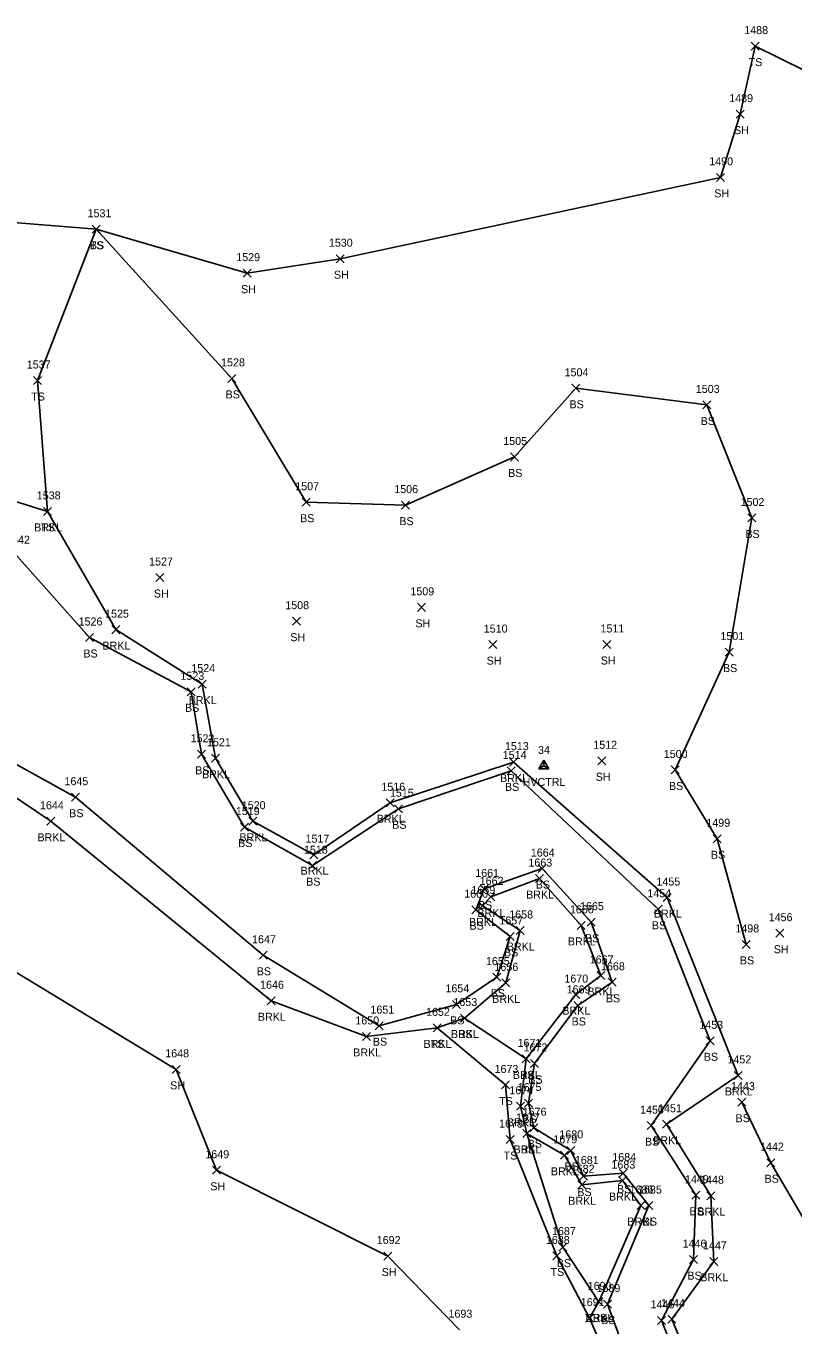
# Model space of a CAD drawing. Extents: x 1754529 to 1755810, y 621660 to 624656.
# Drawn here: x 1754836 to 1755027.6, y 624099.9 to 624424.4 of the extents above; entities that cross this region are included whole.
import ezdxf

# ---------------------------------------------------------------- set-up
doc = ezdxf.new("R2010")
doc.units = 0
for name, color, linetype in [('C_A', 7, 'Continuous'), ('C_I', 7, 'Continuous'), ('CPSM', 7, 'Continuous'), ('L_A', 7, 'Continuous'), ('L_I', 7, 'Continuous'), ('L_TIC', 7, 'Continuous'), ('LAWE', 7, 'Continuous'), ('LELB', 7, 'Continuous'), ('LSOGP', 7, 'Continuous')]:
    doc.layers.add(name, color=color, linetype=linetype)

msp = doc.modelspace()

# ---------------------------------------------------------------- linework, layer by layer
at = {"layer": 'CPSM'}
for p, q in [((1754964.13, 624238.8), (1754965.38, 624240.97)), ((1754966.63, 624238.8), (1754965.38, 624240.97)), ((1754965.38, 624239.53), (1754965.38, 624240.97)), ((1754964.13, 624238.8), (1754965.38, 624239.53)), ((1754964.13, 624238.8), (1754966.63, 624238.8)), ((1754965.38, 624239.53), (1754965.38, 624239.53)), ((1754965.38, 624239.53), (1754966.63, 624238.8))]:
    msp.add_line(p, q, dxfattribs=at)
at = {"layer": 'L_TIC'}
for points in [[(1755017.14, 624418.38), (1755019.14, 624420.38)], [(1755019.14, 624418.38), (1755017.14, 624420.38)], [(1755013.4, 624401.38), (1755015.4, 624403.38)], [(1755015.4, 624401.38), (1755013.4, 624403.38)], [(1755008.48, 624385.59), (1755010.48, 624387.59)], [(1755010.48, 624385.59), (1755008.48, 624387.59)], [(1754852.48, 624372.62), (1754854.48, 624374.62)], [(1754854.48, 624372.62), (1754852.48, 624374.62)], [(1754852.48, 624372.62), (1754854.48, 624374.62)], [(1754854.48, 624372.62), (1754852.48, 624374.62)], [(1754913.43, 624365.26), (1754915.43, 624367.26)], [(1754915.43, 624365.26), (1754913.43, 624367.26)], [(1754890.2, 624361.65), (1754892.2, 624363.65)], [(1754892.2, 624361.65), (1754890.2, 624363.65)], [(1754837.84, 624334.83), (1754839.84, 624336.83)], [(1754839.84, 624334.83), (1754837.84, 624336.83)], [(1754886.4, 624335.36), (1754888.4, 624337.36)], [(1754888.4, 624335.36), (1754886.4, 624337.36)], [(1754972.33, 624332.88), (1754974.33, 624334.88)], [(1754974.33, 624332.88), (1754972.33, 624334.88)], [(1755005.11, 624328.73), (1755007.11, 624330.73)], [(1755007.11, 624328.73), (1755005.11, 624330.73)], [(1754957, 624315.72), (1754959, 624317.72)], [(1754959, 624315.72), (1754957, 624317.72)], [(1754905.01, 624304.42), (1754907.01, 624306.42)], [(1754907.01, 624304.42), (1754905.01, 624306.42)], [(1754929.81, 624303.69), (1754931.81, 624305.69)], [(1754931.81, 624303.69), (1754929.81, 624305.69)], [(1754840.35, 624302.13), (1754842.35, 624304.13)], [(1754842.35, 624302.13), (1754840.35, 624304.13)], [(1754840.35, 624302.13), (1754842.35, 624304.13)], [(1754842.35, 624302.13), (1754840.35, 624304.13)], [(1755016.31, 624300.48), (1755018.31, 624302.48)], [(1755018.31, 624300.48), (1755016.31, 624302.48)], [(1754868.42, 624285.61), (1754870.42, 624287.61)], [(1754870.42, 624285.61), (1754868.42, 624287.61)], [(1754933.8, 624278.16), (1754935.8, 624280.16)], [(1754935.8, 624278.16), (1754933.8, 624280.16)], [(1754902.52, 624274.7), (1754904.52, 624276.7)], [(1754904.52, 624274.7), (1754902.52, 624276.7)], [(1754857.42, 624272.58), (1754859.42, 624274.58)], [(1754859.42, 624272.58), (1754857.42, 624274.58)], [(1754850.86, 624270.62), (1754852.86, 624272.62)], [(1754852.86, 624270.62), (1754850.86, 624272.62)], [(1754951.58, 624268.85), (1754953.58, 624270.85)], [(1754953.58, 624268.85), (1754951.58, 624270.85)], [(1754980.09, 624268.88), (1754982.09, 624270.88)], [(1754982.09, 624268.88), (1754980.09, 624270.88)], [(1755010.7, 624266.98), (1755012.7, 624268.98)], [(1755012.7, 624266.98), (1755010.7, 624268.98)], [(1754878.96, 624258.97), (1754880.96, 624260.97)], [(1754880.96, 624258.97), (1754878.96, 624260.97)], [(1754876.26, 624257.05), (1754878.26, 624259.05)], [(1754878.26, 624257.05), (1754876.26, 624259.05)], [(1754878.78, 624241.44), (1754880.78, 624243.44)], [(1754880.78, 624241.44), (1754878.78, 624243.44)], [(1754882.32, 624240.45), (1754884.32, 624242.45)], [(1754884.32, 624240.45), (1754882.32, 624242.45)], [(1754956.76, 624239.48), (1754958.76, 624241.48)], [(1754958.76, 624239.48), (1754956.76, 624241.48)], [(1754978.86, 624239.82), (1754980.86, 624241.82)], [(1754980.86, 624239.82), (1754978.86, 624241.82)], [(1754956.22, 624237.3), (1754958.22, 624239.3)], [(1754958.22, 624237.3), (1754956.22, 624239.3)], [(1754997.19, 624237.53), (1754999.19, 624239.53)], [(1754999.19, 624237.53), (1754997.19, 624239.53)], [(1754847.32, 624230.72), (1754849.32, 624232.72)], [(1754849.32, 624230.72), (1754847.32, 624232.72)], [(1754925.95, 624229.32), (1754927.95, 624231.32)], [(1754927.95, 624229.32), (1754925.95, 624231.32)], [(1754928.02, 624227.84), (1754930.02, 624229.84)], [(1754930.02, 624227.84), (1754928.02, 624229.84)], [(1754841.19, 624224.7), (1754843.19, 624226.7)], [(1754843.19, 624224.7), (1754841.19, 624226.7)], [(1754889.53, 624223.26), (1754891.53, 624225.26)], [(1754891.53, 624223.26), (1754889.53, 624225.26)], [(1754891.66, 624224.72), (1754893.66, 624226.72)], [(1754893.66, 624224.72), (1754891.66, 624226.72)], [(1755007.68, 624220.34), (1755009.68, 624222.34)], [(1755009.68, 624220.34), (1755007.68, 624222.34)], [(1754906.93, 624216.36), (1754908.93, 624218.36)], [(1754908.93, 624216.36), (1754906.93, 624218.36)], [(1754906.54, 624213.62), (1754908.54, 624215.62)], [(1754908.54, 624213.62), (1754906.54, 624215.62)], [(1754963.91, 624212.89), (1754965.91, 624214.89)], [(1754965.91, 624212.89), (1754963.91, 624214.89)], [(1754963.29, 624210.39), (1754965.29, 624212.39)], [(1754965.29, 624210.39), (1754963.29, 624212.39)], [(1754949.45, 624207.79), (1754951.45, 624209.79)], [(1754951.45, 624207.79), (1754949.45, 624209.79)], [(1754949.02, 624203.56), (1754951.02, 624205.56)], [(1754951.02, 624203.56), (1754949.02, 624205.56)], [(1754951.13, 624205.82), (1754953.13, 624207.82)], [(1754953.13, 624205.82), (1754951.13, 624207.82)], [(1754995.2, 624205.64), (1754997.2, 624207.64)], [(1754997.2, 624205.64), (1754995.2, 624207.64)], [(1754947.34, 624202.62), (1754949.34, 624204.62)], [(1754949.34, 624202.62), (1754947.34, 624204.62)], [(1754992.93, 624202.72), (1754994.93, 624204.72)], [(1754994.93, 624202.72), (1754992.93, 624204.72)], [(1754958.46, 624197.42), (1754960.46, 624199.42)], [(1754960.46, 624197.42), (1754958.46, 624199.42)], [(1754973.73, 624198.69), (1754975.73, 624200.69)], [(1754975.73, 624198.69), (1754973.73, 624200.69)], [(1754976.21, 624199.5), (1754978.21, 624201.5)], [(1754978.21, 624199.5), (1754976.21, 624201.5)], [(1755023.32, 624196.74), (1755025.32, 624198.74)], [(1755025.32, 624196.74), (1755023.32, 624198.74)], [(1754955.98, 624195.94), (1754957.98, 624197.94)], [(1754957.98, 624195.94), (1754955.98, 624197.94)], [(1755014.92, 624193.95), (1755016.92, 624195.95)], [(1755016.92, 624193.95), (1755014.92, 624195.95)], [(1754894.19, 624191.23), (1754896.19, 624193.23)], [(1754896.19, 624191.23), (1754894.19, 624193.23)], [(1754952.63, 624185.76), (1754954.63, 624187.76)], [(1754954.63, 624185.76), (1754952.63, 624187.76)], [(1754954.83, 624184.34), (1754956.83, 624186.34)], [(1754956.83, 624184.34), (1754954.83, 624186.34)], [(1754978.63, 624186.18), (1754980.63, 624188.18)], [(1754980.63, 624186.18), (1754978.63, 624188.18)], [(1754981.43, 624184.47), (1754983.43, 624186.47)], [(1754983.43, 624184.47), (1754981.43, 624186.47)], [(1754972.33, 624181.4), (1754974.33, 624183.4)], [(1754974.33, 624181.4), (1754972.33, 624183.4)], [(1754896.25, 624179.87), (1754898.25, 624181.87)], [(1754898.25, 624179.87), (1754896.25, 624181.87)], [(1754942.51, 624178.97), (1754944.51, 624180.97)], [(1754944.51, 624178.97), (1754942.51, 624180.97)], [(1754972.87, 624178.69), (1754974.87, 624180.69)], [(1754974.87, 624178.69), (1754972.87, 624180.69)], [(1754944.51, 624175.55), (1754946.51, 624177.55)], [(1754946.51, 624175.55), (1754944.51, 624177.55)], [(1754944.51, 624175.55), (1754946.51, 624177.55)], [(1754946.51, 624175.55), (1754944.51, 624177.55)], [(1754920.09, 624170.95), (1754922.09, 624172.95)], [(1754922.09, 624170.95), (1754920.09, 624172.95)], [(1754923.2, 624173.64), (1754925.2, 624175.64)], [(1754925.2, 624173.64), (1754923.2, 624175.64)], [(1754937.68, 624173.1), (1754939.68, 624175.1)], [(1754939.68, 624173.1), (1754937.68, 624175.1)], [(1754937.68, 624173.1), (1754939.68, 624175.1)], [(1754939.68, 624173.1), (1754937.68, 624175.1)], [(1755005.9, 624169.86), (1755007.9, 624171.86)], [(1755007.9, 624169.86), (1755005.9, 624171.86)], [(1754959.97, 624165.35), (1754961.97, 624167.35)], [(1754961.97, 624165.35), (1754959.97, 624167.35)], [(1754959.97, 624165.35), (1754961.97, 624167.35)], [(1754961.97, 624165.35), (1754959.97, 624167.35)], [(1754962.04, 624164.21), (1754964.04, 624166.21)], [(1754964.04, 624164.21), (1754962.04, 624166.21)], [(1754872.5, 624162.73), (1754874.5, 624164.73)], [(1754874.5, 624162.73), (1754872.5, 624164.73)], [(1755012.94, 624161.22), (1755014.94, 624163.22)], [(1755014.94, 624161.22), (1755012.94, 624163.22)], [(1754954.79, 624158.83), (1754956.79, 624160.83)], [(1754956.79, 624158.83), (1754954.79, 624160.83)], [(1754960.55, 624154.31), (1754962.55, 624156.31)], [(1754962.55, 624154.31), (1754960.55, 624156.31)], [(1755013.83, 624154.53), (1755015.83, 624156.53)], [(1755015.83, 624154.53), (1755013.83, 624156.53)], [(1754958.5, 624153.51), (1754960.5, 624155.51)], [(1754960.5, 624153.51), (1754958.5, 624155.51)], [(1754961.87, 624148.15), (1754963.87, 624150.15)], [(1754963.87, 624148.15), (1754961.87, 624150.15)], [(1754991.2, 624148.66), (1754993.2, 624150.66)], [(1754993.2, 624148.66), (1754991.2, 624150.66)], [(1754995.04, 624149), (1754997.04, 624151)], [(1754997.04, 624149), (1754995.04, 624151)], [(1754955.92, 624145.19), (1754957.92, 624147.19)], [(1754957.92, 624145.19), (1754955.92, 624147.19)], [(1754960.15, 624146.72), (1754962.15, 624148.72)], [(1754962.15, 624146.72), (1754960.15, 624148.72)], [(1754960.15, 624146.72), (1754962.15, 624148.72)], [(1754962.15, 624146.72), (1754960.15, 624148.72)], [(1754971.08, 624142.48), (1754973.08, 624144.48)], [(1754973.08, 624142.48), (1754971.08, 624144.48)], [(1754969.5, 624141.25), (1754971.5, 624143.25)], [(1754971.5, 624141.25), (1754969.5, 624143.25)], [(1755021.08, 624139.4), (1755023.08, 624141.4)], [(1755023.08, 624139.4), (1755021.08, 624141.4)], [(1754882.53, 624137.52), (1754884.53, 624139.52)], [(1754884.53, 624137.52), (1754882.53, 624139.52)], [(1754974.3, 624136.07), (1754976.3, 624138.07)], [(1754976.3, 624136.07), (1754974.3, 624138.07)], [(1754984, 624134.93), (1754986, 624136.93)], [(1754986, 624134.93), (1754984, 624136.93)], [(1754984.21, 624136.81), (1754986.21, 624138.81)], [(1754986.21, 624136.81), (1754984.21, 624138.81)], [(1754973.83, 624133.89), (1754975.83, 624135.89)], [(1754975.83, 624133.89), (1754973.83, 624135.89)], [(1754988.57, 624128.7), (1754990.57, 624130.7)], [(1754990.57, 624128.7), (1754988.57, 624130.7)], [(1754990.64, 624128.7), (1754992.64, 624130.7)], [(1754992.64, 624128.7), (1754990.64, 624130.7)], [(1755002.34, 624131.28), (1755004.34, 624133.28)], [(1755004.34, 624131.28), (1755002.34, 624133.28)], [(1755006.1, 624131.16), (1755008.1, 624133.16)], [(1755008.1, 624131.16), (1755006.1, 624133.16)], [(1754925.35, 624116.08), (1754927.35, 624118.08)], [(1754927.35, 624116.08), (1754925.35, 624118.08)], [(1754967.62, 624116.1), (1754969.62, 624118.1)], [(1754969.62, 624116.1), (1754967.62, 624118.1)], [(1754969.15, 624118.32), (1754971.15, 624120.32)], [(1754971.15, 624118.32), (1754969.15, 624120.32)], [(1755001.8, 624115.19), (1755003.8, 624117.19)], [(1755003.8, 624115.19), (1755001.8, 624117.19)], [(1755006.83, 624114.76), (1755008.83, 624116.76)], [(1755008.83, 624114.76), (1755006.83, 624116.76)], [(1754978.15, 624104.63), (1754980.15, 624106.63)], [(1754980.15, 624104.63), (1754978.15, 624106.63)], [(1754978.15, 624104.63), (1754980.15, 624106.63)], [(1754980.15, 624104.63), (1754978.15, 624106.63)], [(1754980.29, 624104.08), (1754982.29, 624106.08)], [(1754982.29, 624104.08), (1754980.29, 624106.08)], [(1754975.77, 624100.58), (1754977.77, 624102.58)], [(1754977.77, 624100.58), (1754975.77, 624102.58)], [(1754975.77, 624100.58), (1754977.77, 624102.58)], [(1754977.77, 624100.58), (1754975.77, 624102.58)], [(1754993.73, 624100.02), (1754995.73, 624102.02)], [(1754995.73, 624100.02), (1754993.73, 624102.02)], [(1754996.35, 624100.33), (1754998.35, 624102.33)], [(1754998.35, 624100.33), (1754996.35, 624102.33)]]:
    msp.add_lwpolyline(points, dxfattribs=at)
at = {"layer": 'LAWE'}
for points in [[(1755011.46, 624067.07), (1754997.35, 624101.33), (1755007.83, 624115.76), (1755007.1, 624132.16), (1754996.04, 624150), (1755013.94, 624162.22), (1754996.2, 624206.64), (1754957.76, 624240.48), (1754926.95, 624230.32), (1754907.93, 624217.36), (1754892.66, 624225.72), (1754883.32, 624241.45), (1754879.96, 624259.97), (1754858.42, 624273.58), (1754841.35, 624303.13), (1754816.47, 624310.82)], [(1754808.82, 624248.13), (1754842.19, 624225.7), (1754897.25, 624180.87), (1754921.09, 624171.95), (1754938.68, 624174.1), (1754945.51, 624176.55), (1754955.83, 624185.34), (1754959.46, 624198.42), (1754950.02, 624204.56), (1754952.13, 624206.82), (1754964.29, 624211.39), (1754974.73, 624199.69), (1754979.63, 624187.18), (1754973.33, 624182.4), (1754960.97, 624166.35), (1754959.5, 624154.51), (1754961.15, 624147.72), (1754970.5, 624142.25), (1754974.83, 624134.89), (1754985, 624135.93), (1754989.57, 624129.7), (1754979.15, 624105.63), (1754976.77, 624101.58), (1754994.95, 624059.8)]]:
    msp.add_lwpolyline(points, dxfattribs=at)
at = {"layer": 'LELB'}
for points in [[(1755139.04, 624115.61), (1755135.04, 624134.99), (1755120.88, 624159.14), (1755108.49, 624174.55), (1755081.03, 624201.93), (1755079.94, 624225.73), (1755076.51, 624247.96), (1755080.69, 624289.64), (1755074.01, 624309.47), (1755073.93, 624332.78), (1755077.13, 624367.68), (1755065.05, 624394.38), (1755036.59, 624410.3), (1755018.14, 624419.38)], [(1754853.48, 624373.62), (1754838.84, 624335.83), (1754841.35, 624303.13)], [(1755015.92, 624194.95), (1755008.68, 624221.34), (1754998.19, 624238.53), (1755011.7, 624267.98), (1755017.31, 624301.48), (1755006.11, 624329.73), (1754973.33, 624333.88), (1754958, 624316.72), (1754930.81, 624304.69), (1754906.01, 624305.42), (1754887.4, 624336.36), (1754853.48, 624373.62)], [(1755009.04, 624065.23), (1754994.73, 624101.02), (1755002.8, 624116.19), (1755003.34, 624132.28), (1754992.2, 624149.66), (1755006.9, 624170.86), (1754993.93, 624203.72), (1754957.22, 624238.3), (1754929.02, 624228.84), (1754907.54, 624214.62), (1754890.53, 624224.26), (1754879.78, 624242.44), (1754877.26, 624258.05), (1754851.86, 624271.62), (1754833.67, 624292.06)], [(1754811.13, 624252.26), (1754848.32, 624231.72), (1754895.19, 624192.23), (1754924.2, 624174.64), (1754943.51, 624179.97), (1754953.63, 624186.76), (1754956.98, 624196.94), (1754948.34, 624203.62), (1754950.45, 624208.79), (1754964.91, 624213.89), (1754977.21, 624200.5), (1754982.43, 624185.47), (1754973.87, 624179.69), (1754963.04, 624165.21), (1754961.55, 624155.31), (1754962.87, 624149.15), (1754972.08, 624143.48), (1754975.3, 624137.07), (1754985.21, 624137.81), (1754991.64, 624129.7), (1754981.29, 624105.08), (1754997.58, 624060.81)], [(1754945.51, 624176.55), (1754960.97, 624166.35)], [(1754938.68, 624174.1), (1754955.79, 624159.83), (1754956.92, 624146.19), (1754968.62, 624117.1), (1754976.77, 624101.58)], [(1755180.41, 624106.3), (1755174.28, 624095.36), (1755173.76, 624074.16), (1755124.51, 624068.87), (1755100.91, 624059), (1755087.06, 624039), (1755072.75, 624037.25), (1755062.63, 624048.39), (1755087.97, 624079.2), (1755106.75, 624088.27), (1755068.94, 624107.54), (1755034.87, 624118.61), (1755022.08, 624140.4), (1755014.83, 624155.53)], [(1754961.15, 624147.72), (1754970.15, 624119.32), (1754979.15, 624105.63)]]:
    msp.add_lwpolyline(points, dxfattribs=at)
at = {"layer": 'LSOGP'}
for points in [[(1755036.59, 624410.3), (1755018.14, 624419.38), (1755014.4, 624402.38), (1755009.48, 624386.59), (1754914.43, 624366.26), (1754891.2, 624362.65), (1754853.48, 624373.62), (1754828.7, 624375.67)], [(1754816.61, 624198.17), (1754873.5, 624163.73), (1754883.53, 624138.52), (1754926.35, 624117.08), (1754944.28, 624098.68)]]:
    msp.add_lwpolyline(points, dxfattribs=at)

# ---------------------------------------------------------------- texts
at = {"layer": 'C_A'}
msp.add_text('HVCTRL', height=2, dxfattribs=at).set_placement((1754960.07, 624234.53))
at = {"layer": 'C_I'}
msp.add_text('34', height=2, dxfattribs=at).set_placement((1754963.91, 624242.53))
at = {"layer": 'L_A'}
for s, p in [('TS', (1755016.55, 624414.38)), ('SH', (1755012.89, 624397.38)), ('SH', (1755007.96, 624381.59)), ('TS', (1754851.89, 624368.62)), ('BS', (1754851.92, 624368.62)), ('SH', (1754912.91, 624361.26)), ('SH', (1754889.69, 624357.65)), ('TS', (1754837.25, 624330.83)), ('BS', (1754885.84, 624331.36)), ('BS', (1754971.77, 624328.88)), ('BS', (1755004.55, 624324.73)), ('BS', (1754956.44, 624311.72)), ('BS', (1754904.45, 624300.42)), ('BRKL', (1754838, 624298.13)), ('TS', (1754839.76, 624298.13)), ('BS', (1754929.25, 624299.69)), ('BS', (1755015.75, 624296.48)), ('SH', (1754867.91, 624281.61)), ('SH', (1754933.28, 624274.16)), ('BRKL', (1754855.07, 624268.58)), ('SH', (1754902.01, 624270.7)), ('BS', (1754850.3, 624266.62)), ('SH', (1754951.07, 624264.85)), ('SH', (1754979.58, 624264.88)), ('BS', (1755010.14, 624262.98)), ('BRKL', (1754876.61, 624254.97)), ('BS', (1754875.7, 624253.05)), ('BS', (1754878.23, 624237.44)), ('BRKL', (1754879.96, 624236.45)), ('BRKL', (1754954.41, 624235.48)), ('SH', (1754978.34, 624235.82)), ('BS', (1754955.66, 624233.3)), ('BS', (1754996.64, 624233.53)), ('BS', (1754846.76, 624226.72)), ('BRKL', (1754923.6, 624225.32)), ('BS', (1754927.47, 624223.84)), ('BRKL', (1754838.83, 624220.7)), ('BS', (1754888.97, 624219.26)), ('BRKL', (1754889.3, 624220.72)), ('BS', (1755007.12, 624216.34)), ('BRKL', (1754904.58, 624212.36)), ('BS', (1754905.98, 624209.62)), ('BRKL', (1754960.94, 624206.39)), ('BS', (1754963.35, 624208.89)), ('BS', (1754948.89, 624203.79)), ('BRKL', (1754948.77, 624201.82)), ('BRKL', (1754992.85, 624201.64)), ('BRKL', (1754946.66, 624199.56)), ('BS', (1754946.78, 624198.62)), ('BS', (1754992.37, 624198.72)), ('BRKL', (1754956.11, 624193.42)), ('BRKL', (1754971.37, 624194.69)), ('BS', (1754975.65, 624195.5)), ('BS', (1754955.42, 624191.94)), ('BS', (1755014.36, 624189.95)), ('SH', (1755022.81, 624192.74)), ('BS', (1754893.63, 624187.23)), ('BS', (1754952.07, 624181.76)), ('BRKL', (1754952.47, 624180.34)), ('BRKL', (1754976.27, 624182.18)), ('BS', (1754980.87, 624180.47)), ('BRKL', (1754969.98, 624177.4)), ('BRKL', (1754893.9, 624175.87)), ('BS', (1754941.95, 624174.97)), ('BS', (1754972.31, 624174.69)), ('BRKL', (1754942.15, 624171.55)), ('BS', (1754943.95, 624171.55)), ('BS', (1754922.64, 624169.64)), ('BRKL', (1754935.32, 624169.1)), ('TS', (1754937.09, 624169.1)), ('BRKL', (1754917.73, 624166.95)), ('BS', (1755005.34, 624165.86)), ('BRKL', (1754957.62, 624161.35)), ('BS', (1754959.42, 624161.35)), ('SH', (1754871.99, 624158.73)), ('BS', (1754961.48, 624160.21)), ('TS', (1754954.2, 624154.83)), ('BRKL', (1755010.59, 624157.22)), ('BRKL', (1754956.14, 624149.51)), ('BS', (1754959.99, 624150.31)), ('BS', (1755013.28, 624150.53)), ('BS', (1754990.64, 624144.66)), ('BRKL', (1754992.69, 624145)), ('BRKL', (1754957.8, 624142.72)), ('BS', (1754959.59, 624142.72)), ('BS', (1754961.31, 624144.15)), ('TS', (1754955.33, 624141.19)), ('BS', (1754970.52, 624138.48)), ('BRKL', (1754967.14, 624137.25)), ('BS', (1755020.52, 624135.4)), ('SH', (1754882.02, 624133.52)), ('BS', (1754973.74, 624132.07)), ('BS', (1754983.65, 624132.81)), ('BRKL', (1754971.47, 624129.89)), ('BRKL', (1754981.65, 624130.93)), ('BS', (1755001.78, 624127.28)), ('BRKL', (1755003.75, 624127.16)), ('BRKL', (1754986.22, 624124.7)), ('BS', (1754990.09, 624124.7)), ('SH', (1754924.84, 624112.08)), ('TS', (1754967.03, 624112.1)), ('BS', (1754968.6, 624114.32)), ('BS', (1755001.24, 624111.19)), ('BRKL', (1755004.48, 624110.76)), ('BRKL', (1754975.8, 624100.63)), ('BS', (1754977.59, 624100.63)), ('BS', (1754979.73, 624100.08))]:
    msp.add_text(s, height=2, dxfattribs=at).set_placement(p)
at = {"layer": 'L_I'}
for s, p in [('1488', (1755015.45, 624422.38)), ('1489', (1755011.7, 624405.38)), ('1490', (1755006.7, 624389.59)), ('1531', (1754851.35, 624376.62)), ('1531', (1754851.35, 624376.62)), ('1530', (1754911.65, 624369.26)), ('1529', (1754888.5, 624365.65)), ('1528', (1754884.71, 624339.36)), ('1537', (1754836.15, 624338.83)), ('1504', (1754970.56, 624336.88)), ('1503', (1755003.34, 624332.73)), ('1505', (1754955.23, 624319.72)), ('1507', (1754903.24, 624308.42)), ('1506', (1754927.99, 624307.69)), ('1538', (1754838.66, 624306.13)), ('1538', (1754838.66, 624306.13)), ('1502', (1755014.53, 624304.48)), ('1542', (1754830.98, 624295.06)), ('1527', (1754866.73, 624289.61)), ('1509', (1754932.02, 624282.16)), ('1508', (1754900.75, 624278.7)), ('1526', (1754849.11, 624274.62)), ('1525', (1754855.73, 624276.58)), ('1510', (1754950.36, 624272.85)), ('1511', (1754979.53, 624272.88)), ('1501', (1755009.49, 624270.98)), ('1524', (1754877.27, 624262.97)), ('1523', (1754874.56, 624261.05)), ('1522', (1754877.09, 624245.44)), ('1521', (1754881.19, 624244.45)), ('1513', (1754955.64, 624243.48)), ('1512', (1754977.73, 624243.82)), ('1514', (1754955.09, 624241.3)), ('1500', (1754995.34, 624241.53)), ('1645', (1754845.58, 624234.72)), ('1516', (1754924.77, 624233.32)), ('1515', (1754926.9, 624231.84)), ('1644', (1754839.45, 624228.7)), ('1519', (1754888.4, 624227.26)), ('1520', (1754889.88, 624228.72)), ('1499', (1755005.98, 624224.34)), ('1517', (1754905.81, 624220.36)), ('1518', (1754905.41, 624217.62)), ('1664', (1754962.12, 624216.89)), ('1663', (1754961.51, 624214.39)), ('1661', (1754948.23, 624211.79)), ('1662', (1754949.34, 624209.82)), ('1455', (1754993.51, 624209.64)), ('1660', (1754945.47, 624206.62)), ('1659', (1754947.27, 624207.56)), ('1454', (1754991.24, 624206.72)), ('1665', (1754974.42, 624203.5)), ('1657', (1754954.24, 624199.94)), ('1658', (1754956.72, 624201.42)), ('1666', (1754971.88, 624202.69)), ('1456', (1755021.57, 624200.74)), ('1498', (1755013.23, 624197.95)), ('1647', (1754892.45, 624195.23)), ('1667', (1754976.84, 624190.18)), ('1655', (1754950.89, 624189.76)), ('1656', (1754953.03, 624188.34)), ('1668', (1754979.65, 624188.47)), ('1646', (1754894.46, 624183.87)), ('1670', (1754970.5, 624185.4)), ('1654', (1754940.77, 624182.97)), ('1669', (1754971.08, 624182.69)), ('1651', (1754922.03, 624177.64)), ('1652', (1754935.94, 624177.1)), ('1652', (1754935.94, 624177.1)), ('1653', (1754942.77, 624179.55)), ('1653', (1754942.77, 624179.55)), ('1650', (1754918.26, 624174.95)), ('1453', (1755004.21, 624173.86)), ('1671', (1754958.8, 624169.35)), ('1671', (1754958.8, 624169.35)), ('1672', (1754960.3, 624168.21)), ('1648', (1754870.76, 624166.73)), ('1452', (1755011.25, 624165.22)), ('1673', (1754953.05, 624162.83)), ('1674', (1754956.76, 624157.51)), ('1675', (1754958.81, 624158.31)), ('1443', (1755012.14, 624158.53)), ('1676', (1754960.08, 624152.15)), ('1450', (1754989.42, 624152.66)), ('1451', (1754993.91, 624153)), ('1678', (1754954.18, 624149.19)), ('1677', (1754958.41, 624150.72)), ('1677', (1754958.41, 624150.72)), ('1679', (1754967.75, 624145.25)), ('1680', (1754969.25, 624146.48)), ('1649', (1754880.78, 624141.52)), ('1442', (1755019.39, 624143.4)), ('1681', (1754973.12, 624140.07)), ('1683', (1754982.26, 624138.93)), ('1684', (1754982.47, 624140.81)), ('1682', (1754972.09, 624137.89)), ('1449', (1755000.64, 624135.28)), ('1448', (1755004.41, 624135.16)), ('1686', (1754986.78, 624132.7)), ('1685', (1754988.9, 624132.7)), ('1687', (1754967.41, 624122.32)), ('1692', (1754923.61, 624120.08)), ('1688', (1754965.88, 624120.1)), ('1446', (1755000.05, 624119.19)), ('1447', (1755005.14, 624118.76)), ('1690', (1754976.32, 624108.63)), ('1690', (1754976.32, 624108.63)), ('1689', (1754978.54, 624108.08)), ('1691', (1754974.6, 624104.58)), ('1691', (1754974.6, 624104.58)), ('1445', (1754992.04, 624104.02)), ('1444', (1754994.66, 624104.33)), ('1693', (1754941.54, 624101.68))]:
    msp.add_text(s, height=2, dxfattribs=at).set_placement(p)

doc.saveas('drawing.dxf')
